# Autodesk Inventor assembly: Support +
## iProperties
Shininess: 41.0
Angle Display Precision: 2
Document Length Units: 11269
Document Angle Units: 11279
Document Time Units: 11290
Document Mass Units: 11283
Document Length Units Precision: 3
Document Angle Units Precision: 2
Created: 2002-09
Part Number: Support +
Document SubType Name: Assemblage
Designer: administrateur
Density: 0.0
Volumn: 0.0
Area: 0.0
PropertySet Name: Model Information
Control State: 0
Master: False
Checked Out: False
Author: administrateur
